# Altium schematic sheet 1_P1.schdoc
size 307 x 218 mm; Symbol: Drawing-Symbol_A4; Device: Drawing-Symbol_A4; @Project Name: Steamdeck Controller Trackpad V1.2; @Page Count: 1; @Update Date: 2025-07-03; @Create Date: 2025-07-02; @Schematic Name: Schematic1; @Page No: 1; @Page Name: P1; Company: EasyEDA.com; Version: V1.0; Page Size: A4; @Create Time: 17:09:18; @Update Time: 16:38:54; Width: 1170; Height: 825; Region Start: 1; X Region Count: 6; Y Region Count: 4; Blade Width: 10; Title Block Position: 3; @Board Name: Board1
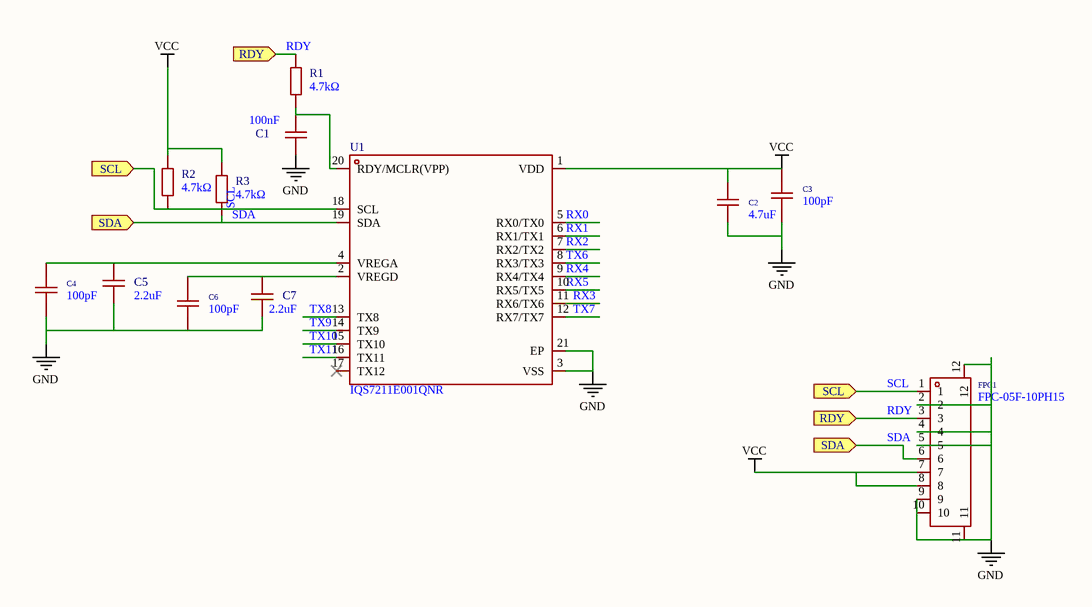
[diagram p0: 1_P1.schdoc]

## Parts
C1  100nF  [C0603]
C2  4.7uF  [C0603]
C3  100pF  [C0603]
C4  100pF  [C0603]
C5  2.2uF  [C0603]
C6  100pF  [C0603]
C7  2.2uF  [C0603]
FPC1  FPC-05F-10PH15  [FPC-SMD_10P-P0.50_XUNPU_FPC-05F-10PH15]
R1  4.7kΩ  [R0603]
R2  4.7kΩ  [R0603]
R3  4.7kΩ  [R0603]
U1  IQS7211E001QNR  [UQFN-20_L3.0-W3.0-P0.40-BL-EP1.7]

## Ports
RDY (in), SCL (in), SDA (in)

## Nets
GND: C1.1 C2.1 C3.1 C4.1 C5.1 C6.1 C7.1 FPC1.2 FPC1.4 FPC1.5 FPC1.9 FPC1.10 FPC1.11 FPC1.12 U1.3(VSS) U1.21(EP)
VCC: C2.2 C3.2 FPC1.7 FPC1.8 R2.2 R3.2 U1.1(VDD)
RDY: FPC1.3 R1.2 ; port RDY
RX0: U1.5(RX0/TX0)
RX1: U1.6(RX1/TX1)
RX2: U1.7(RX2/TX2)
RX3: U1.11(RX6/TX6)
RX4: U1.9(RX4/TX4)
RX5: U1.10(RX5/TX5)
SCL: FPC1.1 R2.1 U1.18(SCL) ; port SCL
SDA: FPC1.6 R3.1 U1.19(SDA) ; port SDA
TX6: U1.8(RX3/TX3)
TX7: U1.12(RX7/TX7)
TX8: U1.13(TX8)
TX9: U1.14(TX9)
TX10: U1.15(TX10)
TX11: U1.16(TX11)
NetC1_2: C1.2 R1.1 U1.20(RDY/MCLR(VPP))
NetC4_2: C4.2 C5.2 U1.4(VREGA)
NetC6_2: C6.2 C7.2 U1.2(VREGD)

Not connected (* = marked no-connect by the designer): U1 17(TX12)*

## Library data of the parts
C1 = CL10B104KA8NNNC: Manufacturer: SAMSUNG(三星); Add into BOM: yes; Tolerance: ±10%
C2 = CL10A475KP8NNNC: Manufacturer: SAMSUNG(三星); Add into BOM: yes; Tolerance: ±10%
C3 C4 C6 = CC0603JRNPO9BN101: Manufacturer: YAGEO(国巨); Add into BOM: yes; Tolerance: ±5%
C5 C7 = CL10A225KP8NNNC: Manufacturer: SAMSUNG(三星); Add into BOM: yes; Tolerance: ±10%
FPC1 = FPC-05F-10PH15: Manufacturer: XUNPU(讯普); Add into BOM: yes; Locking Feature: Clamshell; Number of Contacts: 10P; Pitch: 0.5mm; FFC, FCB Thickness: 0.3mm
R1-R3 = 0603WAF4701T5E: Manufacturer: UNI-ROYAL(厚声); Add into BOM: yes; Tolerance: ±1%; Temperature Coefficient: ±100ppm/℃
U1 = IQS7211E001QNR: Manufacturer: Azoteq; Add into BOM: yes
